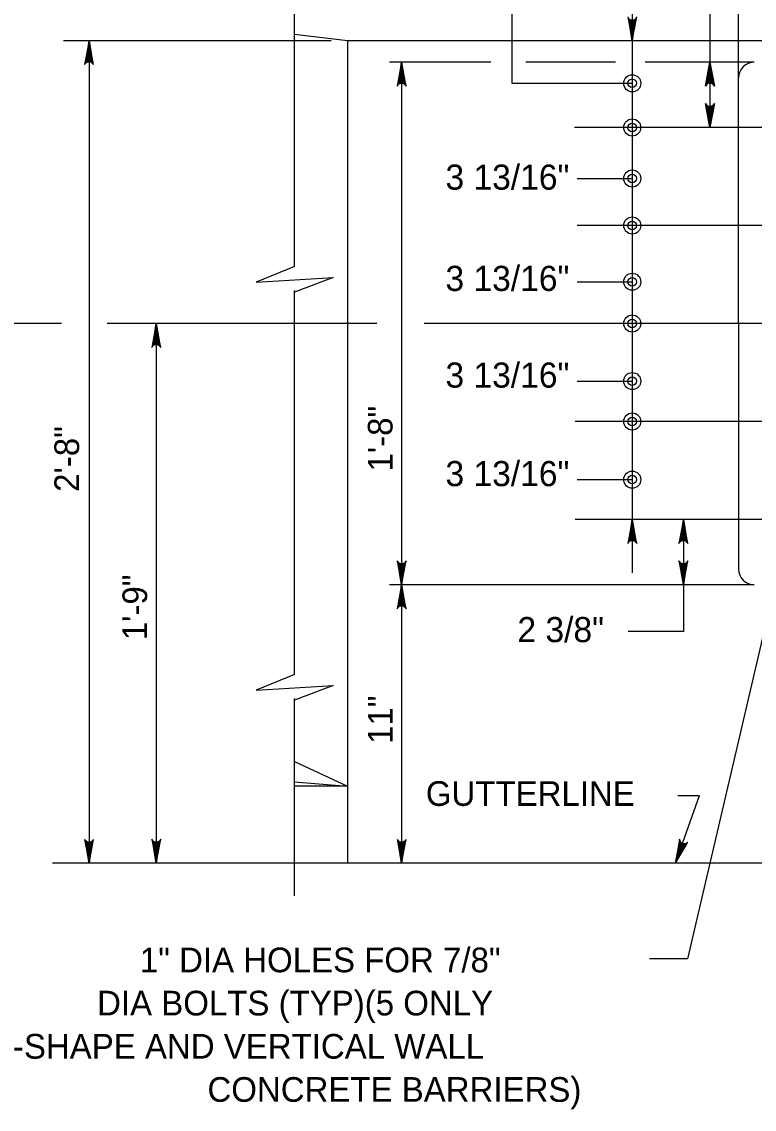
# Model space of a CAD drawing. Extents: x 632007860 to 635435983, y 295418622 to 297794622.
# Drawn here: x 633047395 to 633137894, y 295553678 to 295687995 of the extents above; entities that cross this region are included whole.
import ezdxf

# ---------------------------------------------------------------- set-up
doc = ezdxf.new("R2010")
doc.units = 0
for name, color, linetype in [('8', 7, 'Continuous'), ('S-ABUT', 7, 'Continuous'), ('S-DETL-DIMS', 7, 'Continuous'), ('S-DETL-T120', 7, 'Continuous'), ('S-STEL', 7, 'Continuous')]:
    doc.layers.add(name, color=color, linetype=linetype)

msp = doc.modelspace()

# ---------------------------------------------------------------- linework, layer by layer
at = {"layer": '8'}
for p, q in [((633155462, 295674939), (633115671, 295674939)), ((633231477, 295662835), (633115996, 295662835)), ((633052292, 295650730), (633039239, 295650730)), ((633091264, 295650730), (633057938, 295650730)), ((633142416, 295650730), (633097130, 295650730)), ((633231477, 295638627), (633115762, 295638627)), ((633155174, 295626522), (633115762, 295626522))]:
    msp.add_line(p, q, dxfattribs=at)
at = {"layer": 'S-ABUT'}
for p, q in [((633087647, 295685657), (633081100, 295686436)), ((633240047, 295685657), (633087647, 295685657)), ((633087647, 295685657), (633087647, 295584055)), ((633081100, 295596620), (633087647, 295593580)), ((633081100, 295594126), (633087647, 295593580)), ((633087647, 295593580), (633081100, 295593580)), ((633240047, 295584055), (633081100, 295584055))]:
    msp.add_line(p, q, dxfattribs=at)
at = {"layer": 'S-DETL-DIMS'}
for p, q in [((633135958, 295681072), (633135958, 295727963)), ((633132415, 295697258), (633132415, 295674939)), ((633081100, 295657757), (633081100, 295693303)), ((633122823, 295692445), (633122823, 295619937)), ((633107935, 295692079), (633107935, 295680395)), ((633085619, 295685657), (633052561, 295685657)), ((633055719, 295685657), (633055719, 295584055)), ((633105365, 295683008), (633092832, 295683008)), ((633094324, 295683008), (633094324, 295584055)), ((633120772, 295683008), (633109658, 295683008)), ((633137894, 295683008), (633124418, 295683008)), ((633107935, 295680395), (633122823, 295680395)), ((633116018, 295668639), (633122823, 295668639)), ((633116018, 295655884), (633122823, 295655884)), ((633081100, 295607385), (633081100, 295654796)), ((633091264, 295650730), (633059634, 295650730)), ((633064008, 295650730), (633064008, 295584055)), ((633112577, 295650730), (633097851, 295650730)), ((633116018, 295643615), (633122823, 295643615)), ((633116018, 295631444), (633122823, 295631444)), ((633129141, 295626521), (633129141, 295612701)), ((633141873, 295624681), (633129635, 295572236)), ((633137894, 295618453), (633092832, 295618453)), ((633129141, 295612701), (633122336, 295612701)), ((633081100, 295580027), (633081100, 295604424)), ((633128183, 295584055), (633131119, 295592433)), ((633128472, 295592433), (633131119, 295592433)), ((633081100, 295584055), (633051212, 295584055)), ((633129635, 295572236), (633124969, 295572236))]:
    msp.add_line(p, q, dxfattribs=at)
for points in [[(633122268, 295688616), (633122823, 295685657), (633122347, 295688502)], [(633122426, 295688388), (633122823, 295685657), (633122526, 295688329)], [(633122625, 295688270), (633122823, 295685657), (633122724, 295688253)], [(633122823, 295685657), (633123378, 295688616)], [(633123220, 295688388), (633122823, 295685657), (633123299, 295688502)], [(633123022, 295688270), (633122823, 295685657), (633123121, 295688329)], [(633122823, 295688236), (633122823, 295685657), (633122922, 295688253)], [(633055719, 295685657), (633055164, 295682697), (633055243, 295682811), (633055322, 295682925), (633055421, 295682984), (633055520, 295683043), (633055619, 295683060), (633055719, 295683077), (633055818, 295683060), (633055917, 295683043), (633056016, 295682984), (633056115, 295682925), (633056194, 295682811), (633056273, 295682697), (633055719, 295685657), (633056194, 295682811), (633056115, 295682925), (633055719, 295685657), (633056016, 295682984), (633055917, 295683043), (633055719, 295685657), (633055818, 295683060), (633055719, 295683077), (633055719, 295685657), (633055619, 295683060), (633055520, 295683043), (633055719, 295685657), (633055421, 295682984), (633055322, 295682925), (633055719, 295685657), (633055243, 295682811)], [(633094324, 295683008), (633093770, 295680049), (633093849, 295680163), (633093928, 295680277), (633094027, 295680336), (633094126, 295680395), (633094225, 295680412), (633094324, 295680429), (633094424, 295680412), (633094523, 295680395), (633094622, 295680336), (633094721, 295680277), (633094800, 295680163), (633094879, 295680049), (633094324, 295683008), (633094800, 295680163), (633094721, 295680277), (633094324, 295683008), (633094622, 295680336), (633094523, 295680395), (633094324, 295683008), (633094424, 295680412), (633094324, 295680429), (633094324, 295683008), (633094225, 295680412), (633094126, 295680395), (633094324, 295683008), (633094027, 295680336), (633093928, 295680277), (633094324, 295683008), (633093849, 295680163)], [(633132415, 295683008), (633132970, 295680049), (633132891, 295680163), (633132812, 295680277), (633132712, 295680336), (633132613, 295680395), (633132514, 295680412), (633132415, 295680429), (633132316, 295680412), (633132216, 295680395), (633132117, 295680336), (633132018, 295680277), (633131939, 295680163), (633131860, 295680049), (633132415, 295683008), (633131939, 295680163), (633132018, 295680277), (633132415, 295683008), (633132117, 295680336), (633132216, 295680395), (633132415, 295683008), (633132316, 295680412), (633132415, 295680429), (633132415, 295683008), (633132514, 295680412), (633132613, 295680395), (633132415, 295683008), (633132712, 295680336), (633132812, 295680277), (633132415, 295683008), (633132891, 295680163)], [(633132415, 295674939), (633131860, 295677898), (633131939, 295677784), (633132018, 295677670), (633132117, 295677612), (633132216, 295677553), (633132316, 295677536), (633132415, 295677519), (633132514, 295677536), (633132613, 295677553), (633132712, 295677612), (633132812, 295677670), (633132891, 295677784), (633132970, 295677898), (633132415, 295674939), (633132891, 295677784), (633132812, 295677670), (633132415, 295674939), (633132712, 295677612), (633132613, 295677553), (633132415, 295674939), (633132514, 295677536), (633132415, 295677519), (633132415, 295674939), (633132316, 295677536), (633132216, 295677553), (633132415, 295674939), (633132117, 295677612), (633132018, 295677670), (633132415, 295674939), (633131939, 295677784)], [(633081100, 295657757), (633076337, 295655824), (633085862, 295656400), (633081100, 295654582)], [(633064008, 295650730), (633063453, 295647771), (633063532, 295647885), (633063611, 295647999), (633063710, 295648058), (633063810, 295648117), (633063909, 295648134), (633064008, 295648151), (633064107, 295648134), (633064207, 295648117), (633064306, 295648058), (633064405, 295647999), (633064484, 295647885), (633064563, 295647771), (633064008, 295650730), (633064484, 295647885), (633064405, 295647999), (633064008, 295650730), (633064306, 295648058), (633064207, 295648117), (633064008, 295650730), (633064107, 295648134), (633064008, 295648151), (633064008, 295650730), (633063909, 295648134), (633063810, 295648117), (633064008, 295650730), (633063710, 295648058), (633063611, 295647999), (633064008, 295650730), (633063532, 295647885)], [(633122823, 295626521), (633122268, 295623562), (633122347, 295623676), (633122426, 295623790), (633122526, 295623849), (633122625, 295623908), (633122724, 295623925), (633122823, 295623942), (633122922, 295623925), (633123022, 295623908), (633123121, 295623849), (633123220, 295623790), (633123299, 295623676), (633123378, 295623562), (633122823, 295626521), (633123299, 295623676), (633123220, 295623790), (633122823, 295626521), (633123121, 295623849), (633123022, 295623908), (633122823, 295626521), (633122922, 295623925), (633122823, 295623942), (633122823, 295626521), (633122724, 295623925), (633122625, 295623908), (633122823, 295626521), (633122526, 295623849), (633122426, 295623790), (633122823, 295626521), (633122347, 295623676)], [(633129141, 295626521), (633128586, 295623562), (633128665, 295623676), (633128744, 295623790), (633128843, 295623849), (633128942, 295623908), (633129042, 295623925), (633129141, 295623942), (633129240, 295623925), (633129339, 295623908), (633129439, 295623849), (633129538, 295623790), (633129617, 295623676), (633129696, 295623562), (633129141, 295626521), (633129617, 295623676), (633129538, 295623790), (633129141, 295626521), (633129439, 295623849), (633129339, 295623908), (633129141, 295626521), (633129240, 295623925), (633129141, 295623942), (633129141, 295626521), (633129042, 295623925), (633128942, 295623908), (633129141, 295626521), (633128843, 295623849), (633128744, 295623790), (633129141, 295626521), (633128665, 295623676)], [(633094324, 295618453), (633094879, 295621412), (633094800, 295621298), (633094721, 295621184), (633094622, 295621125), (633094523, 295621067), (633094424, 295621050), (633094324, 295621032), (633094225, 295621050), (633094126, 295621067), (633094027, 295621125), (633093928, 295621184), (633093849, 295621298), (633093770, 295621412), (633094324, 295618453), (633093849, 295621298), (633093928, 295621184), (633094324, 295618453), (633094027, 295621125), (633094126, 295621067), (633094324, 295618453), (633094225, 295621050), (633094324, 295621032), (633094324, 295618453), (633094424, 295621050), (633094523, 295621067), (633094324, 295618453), (633094622, 295621125), (633094721, 295621184), (633094324, 295618453), (633094800, 295621298)], [(633129141, 295618453), (633129696, 295621412), (633129617, 295621298), (633129538, 295621184), (633129439, 295621125), (633129339, 295621067), (633129240, 295621050), (633129141, 295621033), (633129042, 295621050), (633128942, 295621067), (633128843, 295621125), (633128744, 295621184), (633128665, 295621298), (633128586, 295621412), (633129141, 295618453), (633128665, 295621298), (633128744, 295621184), (633129141, 295618453), (633128843, 295621125), (633128942, 295621067), (633129141, 295618453), (633129042, 295621050), (633129141, 295621033), (633129141, 295618453), (633129240, 295621050), (633129339, 295621067), (633129141, 295618453), (633129439, 295621125), (633129538, 295621184), (633129141, 295618453), (633129617, 295621298)], [(633094324, 295618453), (633093770, 295615493), (633093849, 295615607), (633093928, 295615722), (633094027, 295615780), (633094126, 295615839), (633094225, 295615856), (633094324, 295615873), (633094424, 295615856), (633094523, 295615839), (633094622, 295615780), (633094721, 295615722), (633094800, 295615607), (633094879, 295615493), (633094324, 295618453), (633094800, 295615607), (633094721, 295615722), (633094324, 295618453), (633094622, 295615780), (633094523, 295615839), (633094324, 295618453), (633094424, 295615856), (633094324, 295615873), (633094324, 295618453), (633094225, 295615856), (633094126, 295615839), (633094324, 295618453), (633094027, 295615780), (633093928, 295615722), (633094324, 295618453), (633093849, 295615607)], [(633081100, 295607385), (633076337, 295605452), (633085862, 295606028), (633081100, 295604210)], [(633055719, 295584055), (633056273, 295587014), (633056194, 295586900), (633056115, 295586786), (633056016, 295586728), (633055917, 295586669), (633055818, 295586652), (633055719, 295586635), (633055619, 295586652), (633055520, 295586669), (633055421, 295586728), (633055322, 295586786), (633055243, 295586900), (633055164, 295587014), (633055719, 295584055), (633055243, 295586900), (633055322, 295586786), (633055719, 295584055), (633055421, 295586728), (633055520, 295586669), (633055719, 295584055), (633055619, 295586652), (633055719, 295586635), (633055719, 295584055), (633055818, 295586652), (633055917, 295586669), (633055719, 295584055), (633056016, 295586728), (633056115, 295586786), (633055719, 295584055), (633056194, 295586900)], [(633064008, 295584055), (633064563, 295587015), (633064484, 295586900), (633064405, 295586786), (633064306, 295586728), (633064207, 295586669), (633064107, 295586652), (633064008, 295586635), (633063909, 295586652), (633063810, 295586669), (633063710, 295586728), (633063611, 295586786), (633063532, 295586900), (633063453, 295587015), (633064008, 295584055), (633063532, 295586900), (633063611, 295586786), (633064008, 295584055), (633063710, 295586728), (633063810, 295586669), (633064008, 295584055), (633063909, 295586652), (633064008, 295586635), (633064008, 295584055), (633064107, 295586652), (633064207, 295586669), (633064008, 295584055), (633064306, 295586728), (633064405, 295586786), (633064008, 295584055), (633064484, 295586900)], [(633094324, 295584055), (633094879, 295587014), (633094800, 295586900), (633094721, 295586786), (633094622, 295586728), (633094523, 295586669), (633094424, 295586652), (633094324, 295586635), (633094225, 295586652), (633094126, 295586669), (633094027, 295586728), (633093928, 295586786), (633093849, 295586900), (633093770, 295587014), (633094324, 295584055), (633093849, 295586900), (633093928, 295586786), (633094324, 295584055), (633094027, 295586728), (633094126, 295586669), (633094324, 295584055), (633094225, 295586652), (633094324, 295586635), (633094324, 295584055), (633094424, 295586652), (633094523, 295586669), (633094324, 295584055), (633094622, 295586728), (633094721, 295586786), (633094324, 295584055), (633094800, 295586900)], [(633128183, 295584055), (633129708, 295586651), (633129595, 295586571), (633129482, 295586490), (633129368, 295586469), (633129255, 295586447), (633129156, 295586465), (633129057, 295586482), (633128969, 295586532), (633128882, 295586581), (633128808, 295586670), (633128735, 295586759), (633128699, 295586893), (633128664, 295587027), (633128183, 295584055), (633128699, 295586893), (633128735, 295586759), (633128183, 295584055), (633128808, 295586670), (633128882, 295586581), (633128183, 295584055), (633128969, 295586532), (633129057, 295586482), (633128183, 295584055), (633129156, 295586465), (633129255, 295586447), (633128183, 295584055), (633129368, 295586469), (633129482, 295586490), (633128183, 295584055), (633129595, 295586571)]]:
    msp.add_lwpolyline(points, dxfattribs=at)
for centre, radius in [((633122823, 295680395), 1058), ((633122823, 295680395), 529), ((633122823, 295674939), 1058), ((633122823, 295674939), 529), ((633122823, 295668639), 1058), ((633122823, 295668639), 529), ((633122823, 295662835), 1058), ((633122823, 295662835), 529), ((633122823, 295655884), 1058), ((633122823, 295655884), 529), ((633122823, 295650730), 1058), ((633122823, 295650730), 529), ((633122823, 295643615), 1058), ((633122823, 295643615), 529), ((633122823, 295638626), 1058), ((633122823, 295638626), 529), ((633122823, 295631444), 1058), ((633122823, 295631444), 529)]:
    msp.add_circle(centre, radius, dxfattribs=at)
at = {"layer": 'S-STEL'}
for q in [(633135958, 295681072), (633135958, 295620390)]:
    msp.add_line((633135958, 295650731), q, dxfattribs=at)
for centre, start, end in [((633137894, 295681072), 90, 180), ((633137894, 295620390), 180, 270)]:
    msp.add_arc(centre, 1937, start, end, dxfattribs=at)

# ---------------------------------------------------------------- texts
at = {"layer": 'S-DETL-T120'}
for s, height, p in [('3 13/16"', 3102.3, (633099744, 295667251)), ('3 13/16"', 3102.3, (633099744, 295654746)), ('3 13/16"', 3102.3, (633099744, 295642805)), ('3 13/16"', 3102.3, (633099744, 295630638)), ('2 3/8"', 3102.3, (633108635, 295611368)), ('GUTTERLINE', 3048, (633097319, 295591146)), ('1" DIA HOLES FOR 7/8" ', 3048.07, (633061986, 295570597)), ('DIA BOLTS (TYP)(5 ONLY ', 3048.07, (633056706, 295565263)), ('IN F-SHAPE AND VERTICAL WALL', 3048.07, (633038610, 295559929)), ('CONCRETE BARRIERS)', 3048.07, (633070339, 295554595))]:
    msp.add_text(s, height=height, dxfattribs=at).set_placement(p)
for s, p in [('1\'-8"', (633093203, 295632446)), ('2\'-8"', (633054477, 295629934)), ('1\'-9"', (633062887, 295611606)), ('11"', (633093203, 295598796))]:
    msp.add_text(s, height=3048.1, rotation=90, dxfattribs=at).set_placement(p)

doc.saveas('drawing.dxf')
